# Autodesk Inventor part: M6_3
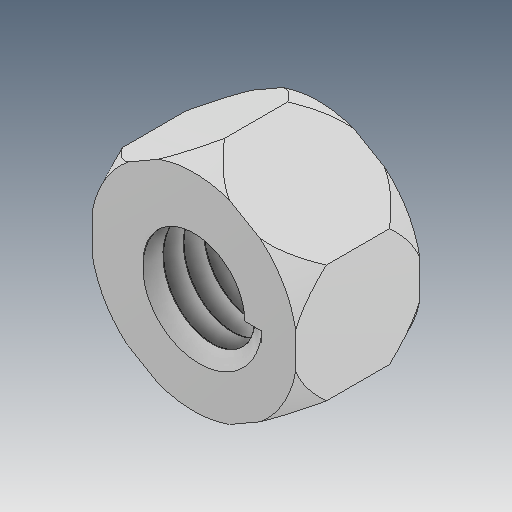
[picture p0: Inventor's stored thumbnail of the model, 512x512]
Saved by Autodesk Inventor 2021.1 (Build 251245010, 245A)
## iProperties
Created: 2021-05
Part Number: M6_3
Material: Ogólny
Document SubType Name: Modeling
Designer: user
Density: 1 g/cm^3
Appearance: Domyślna
Author: user
Revision Number: ÈÎºÎ
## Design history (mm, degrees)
feature "ÊäÈë1"
node "Bryła1"
